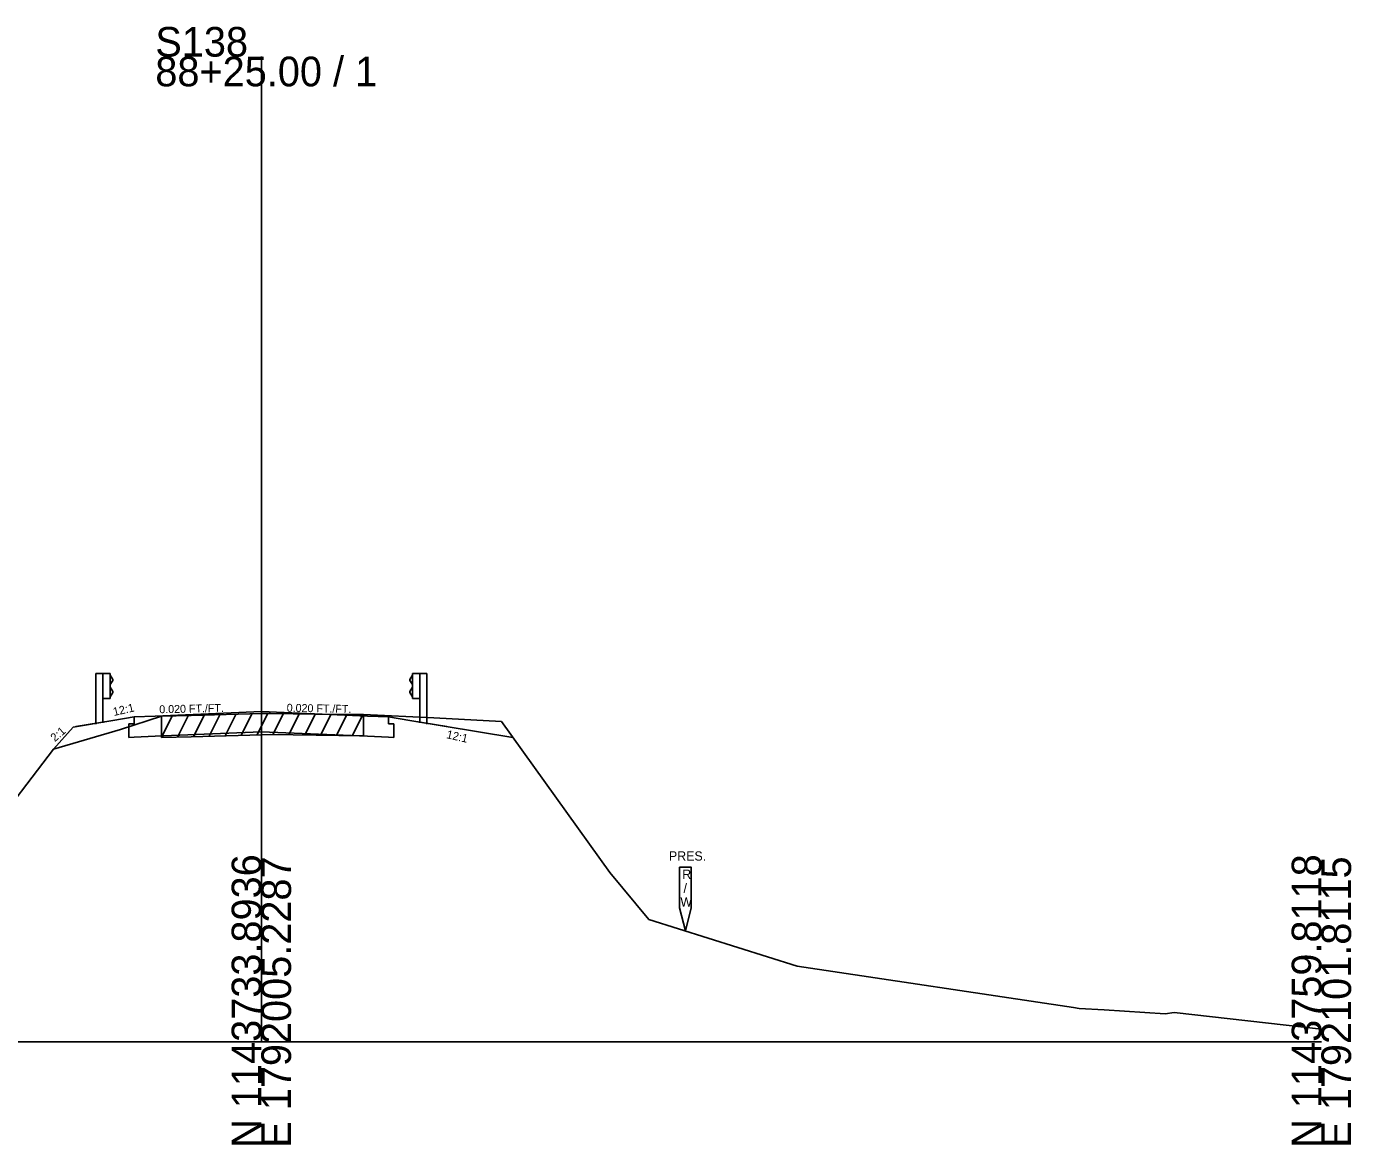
# Model space of a CAD drawing. Extents: x -26 to 1203, y -10 to 19606.
# Drawn here: x 77.8 to 202.8, y 16490.3 to 16595.8 of the extents above; entities that cross this region are included whole.
import ezdxf

# ---------------------------------------------------------------- set-up
doc = ezdxf.new("R2010")
doc.units = 0
for name, color, linetype in [('RD_EX_Driveway', 7, 'Continuous'), ('RD_GPK_XS_Cell', 7, 'Continuous'), ('RD_XS_Base', 7, 'Continuous'), ('RD_XS_EarthShd', 7, 'Continuous'), ('RD_XS_ExGround', 7, 'Continuous'), ('RD_XS_ExPaveRet', 7, 'Continuous'), ('RD_XS_ExRW', 7, 'Continuous'), ('RD_XS_GR', 7, 'Continuous'), ('RD_XS_Pave', 7, 'Continuous'), ('RD_XS_TX_Slope', 7, 'Continuous')]:
    doc.layers.add(name, color=color, linetype=linetype)

msp = doc.modelspace()

# ---------------------------------------------------------------- linework, layer by layer
at = {"layer": 'RD_GPK_XS_Cell'}
for p, q in [((100, 16500), (100, 16592.94)), ((0, 16500), (100, 16500)), ((100, 16500), (200, 16500))]:
    msp.add_line(p, q, dxfattribs=at)
at = {"layer": 'RD_XS_Base'}
for p, q in [((88, 16530.01), (88, 16530.65)), ((112, 16530.01), (112, 16530.65)), ((88, 16530.01), (87.5, 16529.99)), ((87.5, 16528.72), (87.5, 16529.99)), ((90, 16528.83), (100, 16529.24)), ((110, 16528.83), (100, 16529.24)), ((112, 16530.01), (112.5, 16529.99)), ((112.5, 16528.72), (112.5, 16529.99)), ((88, 16528.74), (87.5, 16528.72)), ((88, 16528.74), (90, 16528.83)), ((112, 16528.74), (110, 16528.83)), ((112, 16528.74), (112.5, 16528.72))]:
    msp.add_line(p, q, dxfattribs=at)
at = {"layer": 'RD_XS_EarthShd'}
for p, q in [((86, 16530.32), (82.25, 16529.69)), ((86, 16530.32), (82.5, 16529.73)), ((88, 16530.65), (86, 16530.32)), ((112, 16530.65), (114, 16530.32)), ((114, 16530.32), (117.5, 16529.73)), ((114, 16530.32), (123.73, 16528.69)), ((80.4, 16527.6), (82.25, 16529.69))]:
    msp.add_line(p, q, dxfattribs=at)
at = {"layer": 'RD_XS_ExGround'}
msp.add_lwpolyline([(68.09, 16511.51), (80.4, 16527.6), (86.71, 16529.47), (90.59, 16530.72), (93.37, 16530.77), (100, 16530.96), (100.88, 16530.98), (107.31, 16530.89), (109.63, 16530.87), (116.27, 16530.56), (122.65, 16530.21), (132.86, 16515.97), (136.56, 16511.53), (150.56, 16507.14), (176.62, 16503.22), (177.14, 16503.14), (179.51, 16503.01), (185.26, 16502.63), (186.1, 16502.75), (200, 16501.18)], dxfattribs=at)
at = {"layer": 'RD_XS_ExPaveRet'}
for p, q in [((90.59, 16528.72), (91.6, 16530.74)), ((90.59, 16528.72), (90.59, 16530.72)), ((92.09, 16528.74), (93.1, 16530.76)), ((93.59, 16528.78), (94.6, 16530.8)), ((95.09, 16528.82), (96.1, 16530.85)), ((96.59, 16528.86), (97.6, 16530.89)), ((98.09, 16528.9), (99.1, 16530.93)), ((99.59, 16528.94), (100.6, 16530.97)), ((101.09, 16528.98), (102.08, 16530.96)), ((102.59, 16528.96), (103.58, 16530.94)), ((104.09, 16528.94), (105.08, 16530.92)), ((105.59, 16528.91), (106.58, 16530.9)), ((107.09, 16528.89), (108.08, 16530.88)), ((108.59, 16528.88), (109.58, 16530.87)), ((109.63, 16530.87), (109.63, 16528.87)), ((90.59, 16528.72), (93.37, 16528.77)), ((93.37, 16528.77), (100, 16528.96)), ((100, 16528.96), (100.88, 16528.98)), ((100.88, 16528.98), (107.31, 16528.89)), ((107.31, 16528.89), (109.63, 16528.87))]:
    msp.add_line(p, q, dxfattribs=at)
at = {"layer": 'RD_XS_ExRW'}
msp.add_lwpolyline([(139.45, 16516.46), (140.55, 16516.46), (140.55, 16512.64), (140, 16510.45), (139.45, 16512.64)], close=True, dxfattribs=at)
at = {"layer": 'RD_XS_GR'}
for p, q in [((84.4, 16534.73), (84.4, 16529.97)), ((85.06, 16534.73), (84.4, 16534.73)), ((85.06, 16534.73), (85.06, 16530.08)), ((85.73, 16534.73), (85.06, 16534.73)), ((85.73, 16532.4), (85.73, 16534.73)), ((85.73, 16534.59), (86, 16534.19)), ((86, 16534.09), (85.73, 16533.69)), ((86, 16534.19), (86, 16534.09)), ((114.27, 16534.59), (114, 16534.19)), ((114, 16534.19), (114, 16534.09)), ((114, 16534.09), (114.27, 16533.69)), ((114.27, 16532.4), (114.27, 16534.73)), ((114.27, 16534.73), (114.94, 16534.73)), ((114.94, 16534.73), (114.94, 16530.08)), ((114.94, 16534.73), (115.6, 16534.73)), ((115.6, 16534.73), (115.6, 16529.97)), ((86, 16533.05), (85.73, 16533.45)), ((85.73, 16532.55), (86, 16532.95)), ((86, 16532.95), (86, 16533.05)), ((114, 16533.05), (114.27, 16533.45)), ((114, 16532.95), (114, 16533.05)), ((114.27, 16532.55), (114, 16532.95)), ((85.73, 16532.4), (85.06, 16532.4)), ((114.27, 16532.4), (114.94, 16532.4))]:
    msp.add_line(p, q, dxfattribs=at)
at = {"layer": 'RD_XS_Pave'}
for p, q in [((88, 16530.65), (90, 16530.73)), ((90, 16530.73), (100, 16531.15)), ((110, 16530.73), (100, 16531.15)), ((112, 16530.65), (110, 16530.73))]:
    msp.add_line(p, q, dxfattribs=at)

# ---------------------------------------------------------------- texts
at = {"layer": 'RD_EX_Driveway'}
msp.add_text('541.48', height=0.0975, rotation=90, dxfattribs=at).set_placement((100.1, 16530.96))
at = {"layer": 'RD_GPK_XS_Cell'}
for s, p in [('S138', (90, 16592.94)), ('88+25.00 / 1', (90, 16590.14))]:
    msp.add_text(s, height=2.8, dxfattribs=at).set_placement(p)
for s, p in [('N 1143733.8936', (100, 16490)), ('E 1792005.2287', (102.8, 16490)), ('N 1143759.8118', (200, 16490)), ('E 1792101.8115', (202.8, 16490))]:
    msp.add_text(s, height=2.8, rotation=90, dxfattribs=at).set_placement(p)
at = {"layer": 'RD_XS_ExRW'}
for s, p in [('PRES.', (138.45, 16517.09)), ('R', (139.71, 16515.37)), ('/', (139.83, 16514.06)), ('W', (139.53, 16512.75))]:
    msp.add_text(s, height=0.875, dxfattribs=at).set_placement(p)
at = {"layer": 'RD_XS_TX_Slope'}
for s, height, rotation, p in [('12:1', 0.778, 12.7511, (86.1, 16530.73)), ('0.020 FT./FT.', 0.7518, 1.1916, (90.38, 16530.99)), ('0.020 FT./FT.', 0.7518, 358.8084, (102.39, 16531.14)), ('2:1', 0.778, 40.6589, (80.52, 16528.26)), ('12:1', 0.778, 347.2489, (117.41, 16528.65))]:
    msp.add_text(s, height=height, rotation=rotation, dxfattribs=at).set_placement(p)

doc.saveas('drawing.dxf')
